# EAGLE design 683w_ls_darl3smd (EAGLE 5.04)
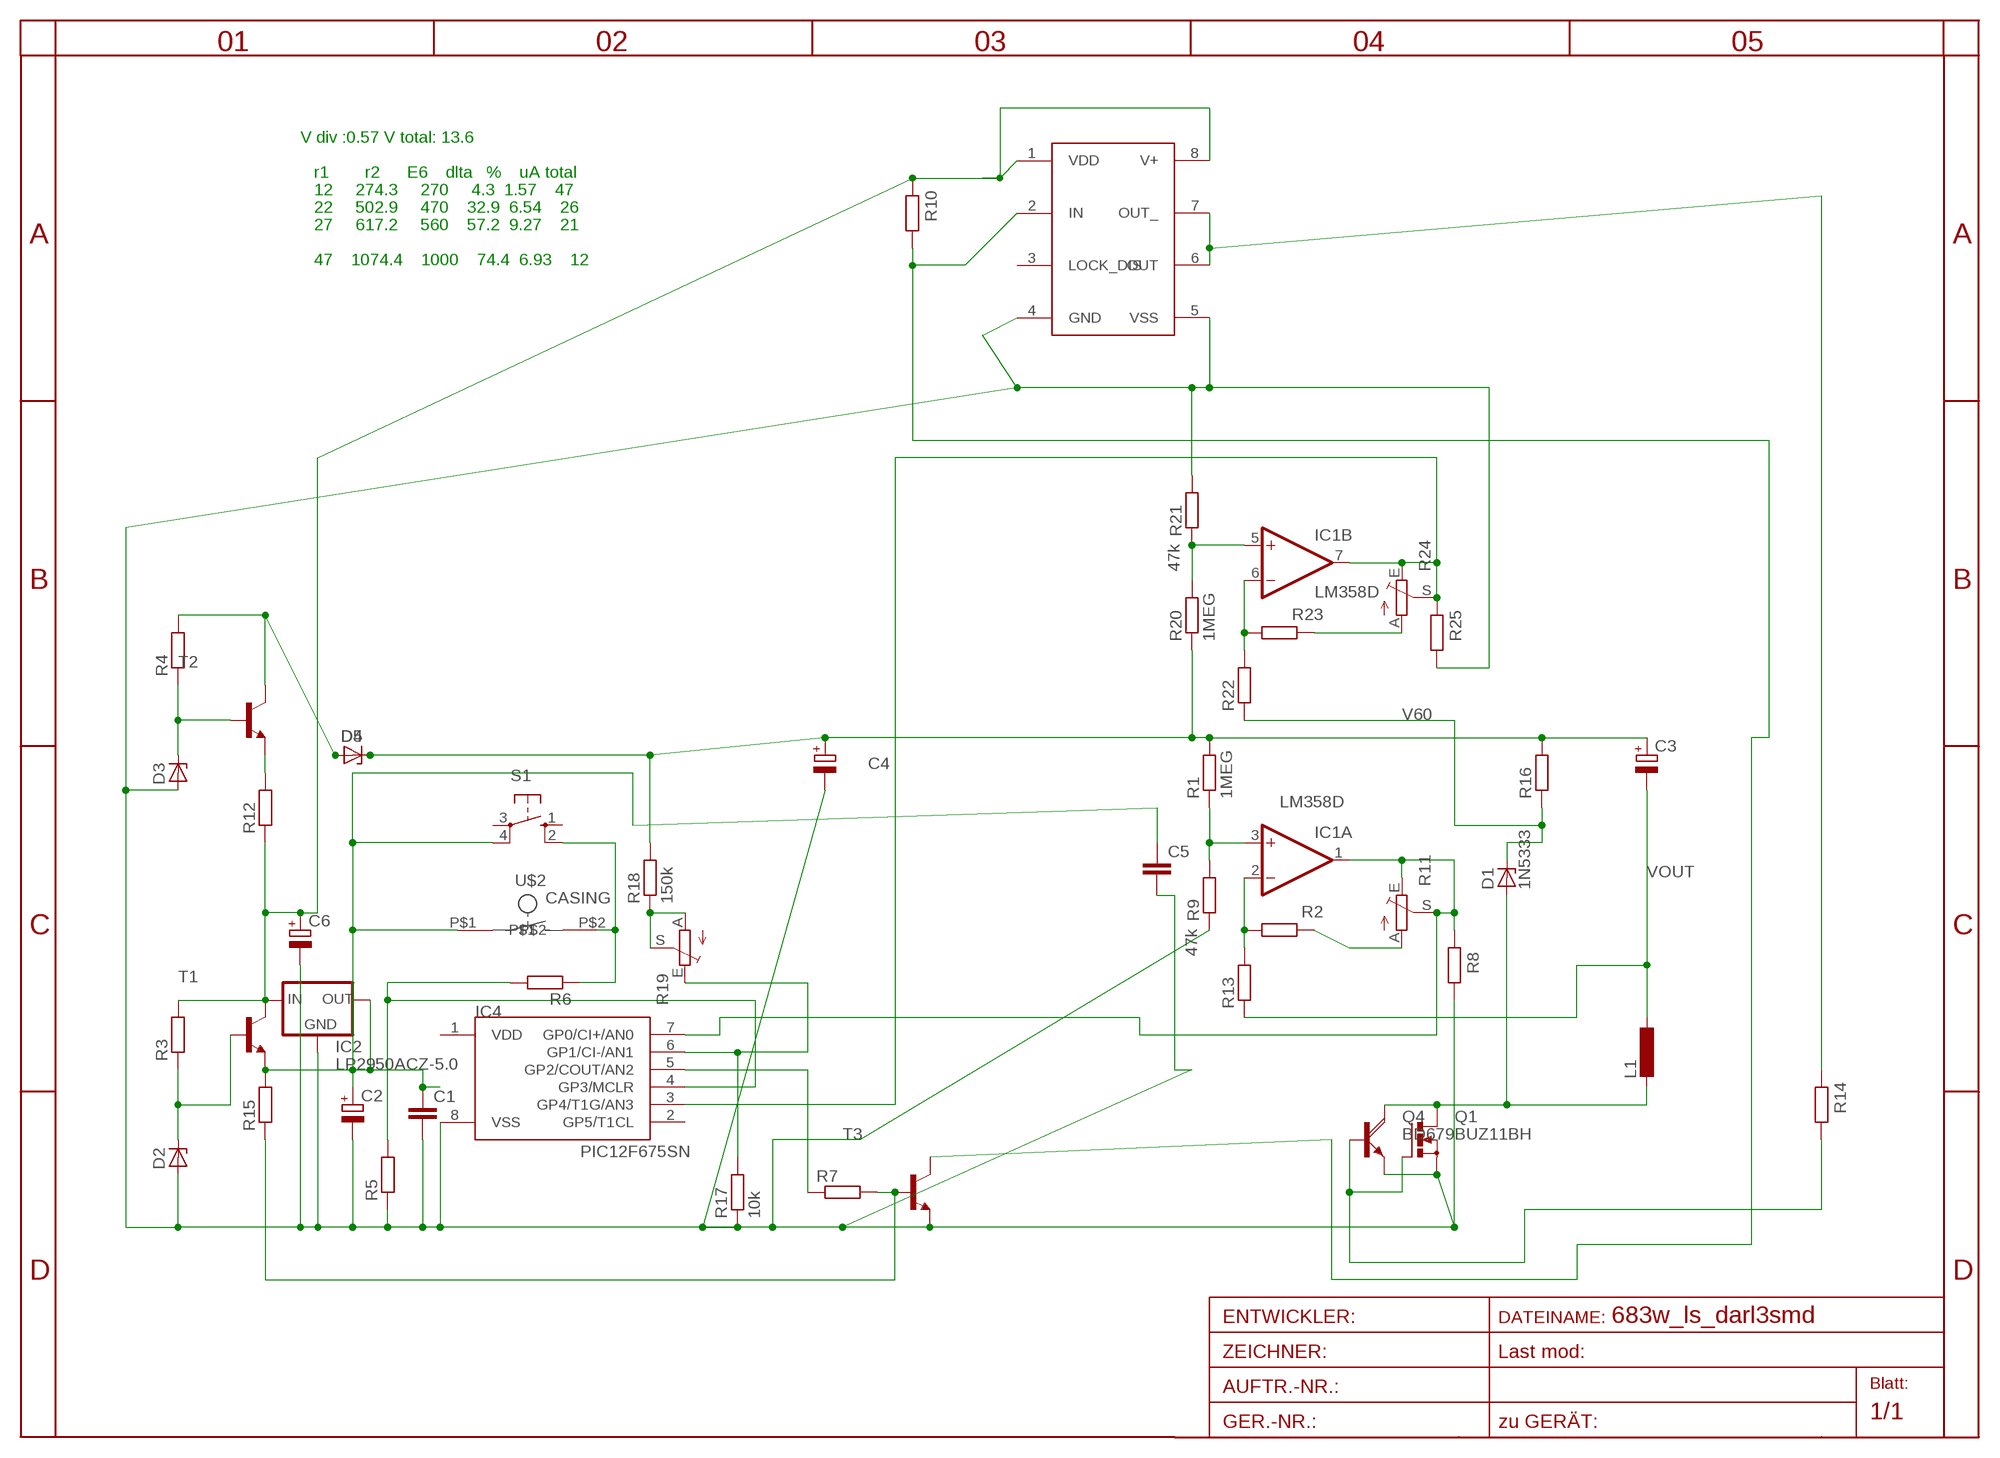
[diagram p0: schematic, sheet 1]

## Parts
C1  C-EUC1206  [C1206]
C2  CPOL-EUSANYO_SMD_E12  [SANYO-OSCON_SMD_E12]
C3  CPOL-EUE5-8.5  [E5-8,5]
C4  CPOL-EUE5-8.5  [E5-8,5]
C5  C-EUC1206  [C1206]
C6  CPOL-EUSANYO_SMD_E12  [SANYO-OSCON_SMD_E12]
D1  1N5333  [C1702-15]
D2  ZENER-DIODESOT23  [SOT23]
D3  ZENER-DIODESMB  [SMB]
D4  ZENER-DIODESMB  [SMB]
D5  ZENER-DIODESMB  [SMB]
IC1  LM358D  [SO08]
IC2  LP2950ACZ-5.0  [TO92]
IC3  TC4432X  [SO-08]
IC4  PIC12F675SN  [SO-08]
L1  L-EU2200-15.24  [2200-15.24]
Q1  BUZ11BH  [TO220BH]
Q4  BD679  [TO126AV]
R1  1MEG  R-EU_R0805  [R0805]
R2  R-EU_R0805  [R0805]
R3  R-EU_R0805  [R0805]
R4  R-EU_R0805  [R0805]
R5  R-EU_R0805  [R0805]
R6  R-EU_M1206  [M1206]
R7  R-EU_R0805  [R0805]
R8  R-EU_R0805  [R0805]
R9  47k  R-EU_R0805  [R0805]
R10  R-EU_R0805  [R0805]
R11  TRIM_EU-CA6V  [CA6V]
R12  R-EU_R0805  [R0805]
R13  R-EU_R0805  [R0805]
R14  R-EU_0207/10  [0207/10]
R15  R-EU_R0805  [R0805]
R16  R-EU_0411/12  [0411/12]
R17  10k  R-EU_R0805  [R0805]
R18  150k  R-EU_R0805  [R0805]
R19  TRIM_EU-CA6V  [CA6V]
R20  1MEG  R-EU_R0805  [R0805]
R21  47k  R-EU_R0805  [R0805]
R22  R-EU_R0805  [R0805]
R23  R-EU_R0805  [R0805]
R24  TRIM_EU-CA6V  [CA6V]
R25  R-EU_R0805  [R0805]
S1  10-XX  [B3F-10XX]
T1  BC846BLT1-NPN-SOT23-BEC  [SOT23-BEC]
T2  BC846BLT1-NPN-SOT23-BEC  [SOT23-BEC]
T3  BC846BLT1-NPN-SOT23-BEC  [SOT23-BEC]
U$2  CASING  [CASING]

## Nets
BB: IC3.2(IN) R10.1 T3.C
HOTSPOT: D1.A L1.2 Q1.D Q4.C
N$1: IC1.1(A:OUT) IC4.7(GP0/CI+/AN0) R8.2 R11.E R11.S
N$2: R2.1 R11.A
N$3: Q1.G Q4.B R14.1
N$5: IC4.4(GP3/MCLR) R5.2 R6.2
N$6: D2.3(C) R3.1 T1.B
N$7: R6.1 S1.2(S1) U$2.P$2
N$8: IC1.3(A:+IN) R1.1 R9.2
N$9: IC4.5(GP2/COUT/AN2) R7.1
N$11: IC3.6(OUT) IC3.7(OUT_) R14.2
N$12: D3.C R4.1 T2.B
N$13: R18.1 R19.A R19.S
N$15: IC1.2(A:-IN) R2.2 R13.2
N$17: R7.2 R15.1 T3.B
N$21: D4.A D5.A R4.2 T2.C
N$22: R12.2 T2.E
N$23: D1.C R16.1 R22.1
N$24: IC1.5(B:+IN) R20.2 R21.1
N$25: IC1.6(B:-IN) R22.2 R23.2
N$26: IC4.6(GP1/CI-/AN1) R17.2 R19.E
N$27: R23.1 R24.A
N$28: IC1.7(B:OUT) IC4.3(GP4/T1G/AN3) R24.E R24.S R25.2
V60: C3.+ C4.+ D4.C D5.C R1.2 R16.2 R18.2 R20.1
V+: C1.1 C2.+ C5.1 IC2.1(OUT) R15.2 S1.4(P1) T1.E U$2.P$1
V-: C1.2 C2.- C4.- C5.2 C6.- D2.1(A) D3.A IC2.2(GND) IC3.4(GND) IC3.5(VSS) IC4.8(VSS) Q1.S Q4.E R5.1 R8.1 R9.1 R17.1 R21.2 R25.1 T3.E
VCC: C6.+ IC2.3(IN) IC3.1(VDD) IC3.8(V+) R3.2 R10.2 R12.1 T1.C
VOUT: C3.- L1.1 R13.1
Unconnected: IC3.3(LOCK_DIS) IC4.2(GP5/T1CL) S1.1(S) S1.3(P)

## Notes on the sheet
- V div :0.57 V total: 13.6
- r1        r2      E6    dlta   %    uA total
- 12     274.3     270     4.3  1.57    47
- 22     502.9     470    32.9  6.54    26
- 27     617.2     560    57.2  9.27    21
- 47    1074.4    1000    74.4  6.93    12

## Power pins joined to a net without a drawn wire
V+: IC1.8(P:V+)
V-: IC1.4(P:V-)
VDD: IC4.1(VDD)

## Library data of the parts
C1 C5 = rcl:C-EU: CAPACITOR, European symbol
C2-C4 C6 = rcl:CPOL-EU: POLARIZED CAPACITOR, European symbol
D1 = diode-1:1N5333: Z DIODE
D2-D5 = diode-1:ZENER-DIODE: Z-Diode
IC1 = linear4:LM358: OP AMP
IC2 = v-reg:LP2950?*: Source: http://cache.national.com/ds/LP/LP2950.pdf
IC3 = microchip:TC4432
IC4 = microchip-5:PIC12F6*: uPC nW 1k Program Flash memory 2x Timer Comparator 10b A/D converter/ 4xIN
L1 = rcl:L-EU: INDUCTOR, European symbol
Q1 = transistor-power:BUZ11: N-CHANNEL MOS FET
Q4 = transistor-power:BD679: NPN DARLINGTON TRANSISTOR
R1-R6 R8-R10 R12 R14 R15 R20 R21 R23 R25 = rcl:R-EU_: RESISTOR, European symbol
R7 R13 R16-R18 R22 = rcl-2:R-EU_: RESISTOR, European symbol
R11 R19 R24 = pot:TRIM_EU-: POTENTIOMETER
S1 = switch-omron:10-XX: OMRON SWITCH
T1-T3 = transistor-neu-to92:*-NPN-: NPN Transistror
U$2 = button:CASING

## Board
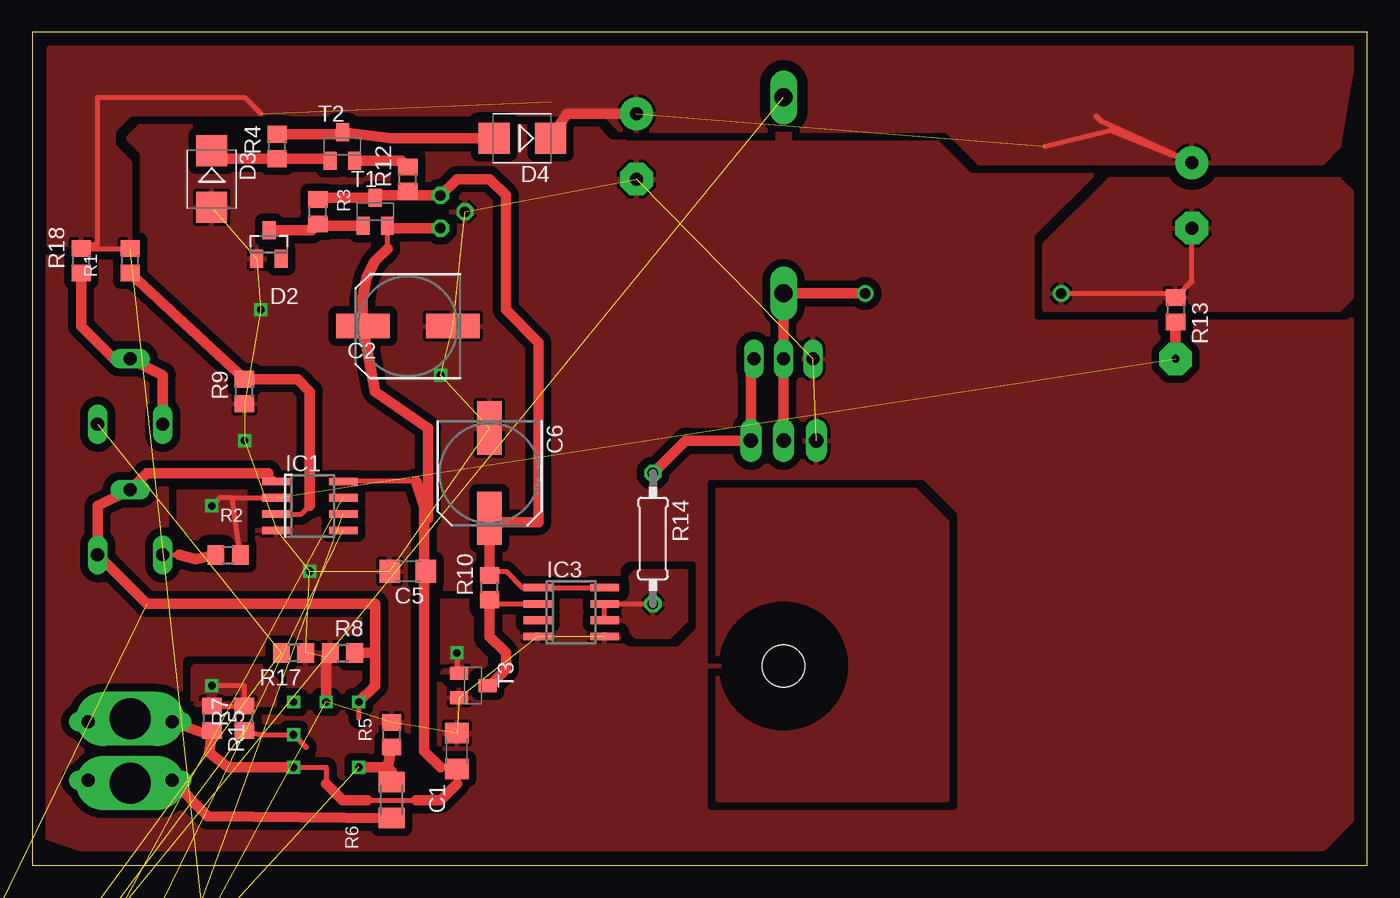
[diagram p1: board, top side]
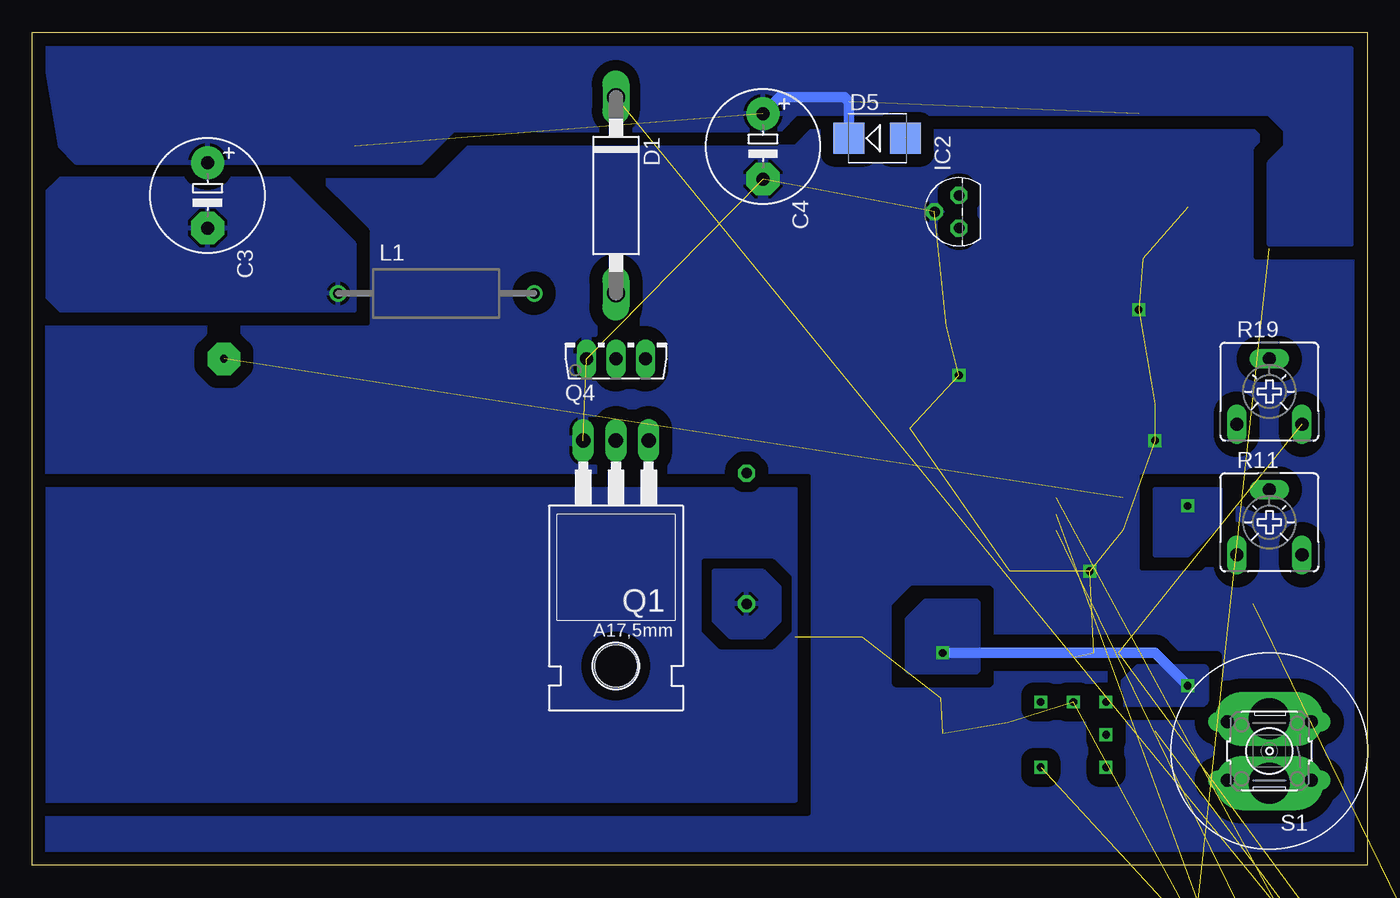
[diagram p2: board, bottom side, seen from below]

Size 103.81 x 64.76 mm. Coordinates in mm from the lower left corner, seen from the top.
Outline: 0,0 103.81,0 103.81,64.76 0,64.76 0,0
Copper layers (1*16): Top 0.035mm / dielectric 1.5mm / Bottom 0.035mm
Design rules "default": minimum track width 10mil, minimum drill 24mil, track to track 8mil, track to pad 8mil, pad to pad 8mil, via to via 8mil, smd to smd 8mil, copper to edge 40mil, drill to drill 8mil, minimum pad ring 10mil, minimum via ring 8mil, stop-mask expansion 4mil, vias tented up to drill 0mil, thermal gap 10mil

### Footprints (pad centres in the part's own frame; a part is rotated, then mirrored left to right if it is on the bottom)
C1206 = smd 1.6 x 1.8: 1 -1.4,0; 2 1.4,0
SANYO-OSCON_SMD_E12 = smd 4.15 x 1.9: + 3.5,0; - -3.5,0
E5-8,5 = drill 1.016 pad 2.54 round: + -2.54,0 | drill 1.016 pad 2.54 octagon: - 2.54,0
C1702-15 = drill 1.397 long: A 7.62,0; C -7.62,0
SOT23 = smd 1 x 1.4: 1 -0.95,-1.1; 2 0.95,-1.1; 3 0,1.1
SMB = smd 2.4 x 2.4: A 2.2,0; C -2.2,0
SO08 = smd 0.6 x 2.2: 1 -1.905,-2.6; 2 -0.635,-2.6; 3 0.635,-2.6; 4 1.905,-2.6; 5 1.905,2.6; 6 0.635,2.6; 7 -0.635,2.6; 8 -1.905,2.6
TO92 = drill 0.813 octagon: 1 -1.27,0; 2 0,1.905; 3 1.27,0
SO-08 = smd 0.6 x 2.2: 1 -1.905,-2.6; 2 -0.635,-2.6; 3 0.635,-2.6; 4 1.905,-2.6; 5 1.905,2.6; 6 0.635,2.6; 7 -0.635,2.6; 8 -1.905,2.6
2200-15.24 = drill 0.8 pad 1.27 round: 1 -7.62,0; 2 7.62,0
TO220BH = drill 1.118 long: D 0,-6.35; G -2.54,-6.35; S 2.54,-6.35 | hole 3.302: 0,11.176
TO126AV = drill 1.016 long: B 2.286,-1.27; C 0,-1.27; E -2.286,-1.27
R0805 = smd 1.3 x 1.5: 1 -0.95,0; 2 0.95,0
M1206 = smd 1.6 x 2: 1 -1.4,0; 2 1.4,0
CA6V = drill 1.016 long: A -2.54,-2.54; E 2.54,-2.54; S 0,2.54
0207/10 = drill 0.813 octagon: 1 -5.08,0; 2 5.08,0
0411/12 = drill 0.914 octagon: 1 -6.35,0; 2 6.35,0
B3F-10XX = drill 1.016 long: 1 -3.251,2.261; 2 3.251,2.261; 3 -3.251,-2.261; 4 3.251,-2.261
SOT23-BEC = smd 1 x 1.4: B -0.95,-1.1; C 0,1.1; E 0.95,-1.1
CASING = drill 3.2 pad 3.81 long: P$1 -2.5,0; P$2 2.5,0

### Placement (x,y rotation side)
C1  33.02,8.89 90 top
C2  29.21,41.91 180 top
C3  90.17,52.07 270 bottom
C4  46.99,55.88 270 bottom
C5  29.21,22.86 180 top
C6  35.56,30.48 270 top
D1  58.42,52.07 270 bottom
D2  18.41,48.26 0 top
D3  13.97,53.34 270 top
D4  38.1,56.52 180 top
D5  38.1,56.52 0 bottom
IC1  21.59,27.94 270 top
IC2  31.75,50.8 90 bottom
IC3  41.91,19.68 270 top
IC4  not placed on the board
L1  72.39,44.45 0 bottom
Q1  58.42,26.67 180 bottom
Q4  58.42,40.64 0 bottom
R1  7.62,46.99 90 top
R2  15.24,24.13 0 top
R3  22.23,50.8 90 top
R4  19.05,55.88 90 top
R5  27.94,10.16 270 top
R6  27.94,5.08 90 top
R7  16.51,11.43 90 top
R8  24.13,16.51 0 top
R9  16.51,36.83 90 top
R10  35.56,21.59 90 top
R11  7.62,26.67 0 bottom
R12  29.21,53.34 90 top
R13  88.9,43.18 270 top
R14  48.26,25.4 270 top
R15  13.97,11.43 270 top
R16  not placed on the board
R17  20.32,16.51 180 top
R18  3.81,46.99 90 top
R19  7.62,36.83 0 bottom
R20  not placed on the board
R21  not placed on the board
R22  not placed on the board
R23  not placed on the board
R24  not placed on the board
R25  not placed on the board
S1  7.62,8.89 180 bottom
T1  26.67,50.8 0 top
T2  24.13,55.88 0 top
T3  34.29,13.97 270 top
U$2  7.62,8.89 270 bottom

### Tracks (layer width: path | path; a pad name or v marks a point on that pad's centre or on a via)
BB
  Top 0.406: T3.C 35.56,13.97 | IC3.2 35.88,20.32 R10.1
  Top 0.813: R10.1 35.56,17.78 36.83,16.51 36.83,15.24 35.56,13.97
HOTSPOT
  Top 0.813: L1.2 D1.A Q4.C Q1.D
N$1  (via drill 0.6)  (1 unrouted)
  Top 0.406: v25.4,12.7 25.4,11.43 | 18.36,30.48 IC1.1
  Top 0.813: 26.67,16.51 26.67,20.32 8.89,20.32 R11.E 5.08,27.94 R11.S 8.89,30.48 18.36,30.48 | 26.67,16.51 26.67,13.97 v25.4,12.7 | 26.67,16.51 R8.2
N$2
  Top 0.406: R11.A 11.43,24.13
  Top 0.813: 11.43,24.13 12.7,23.81 R2.1
N$3
  Top 0.406: 55.88,39.12 Q4.B
  Top 0.813: R14.1 50.8,33.02 Q1.G 55.88,39.12
N$4  (via drill 0.6)
  other vias: 20.32,12.7
N$5  (1 unrouted)
  Top 0.813: 27.62,7.62 25.4,7.62 | 27.62,7.62 R5.2 | R6.2 27.94,7.3 27.62,7.62
N$6
  Top 0.406: 22.38,49.7 R3.1 21.73,49.36
  Top 0.813: 22.38,49.7 T1.B | D2.3 21.73,49.36
N$7
  Top 0.813: R6.1 13.65,3.81 S1.2 10.63,6.39 U$2.P$2
N$8
  Top 0.406: 21.59,27.94 20.95,27.3 IC1.3
  Top 0.813: R1.1 R9.2 20.64,37.78 21.59,36.83 21.59,27.94
N$9  (1 unrouted)
  Top 0.406: 21.34,9.14 20.32,10.16 17.78,10.16 R7.1
N$10  (via drill 0.6)
  other vias: 22.86,12.7
N$11
  Top 0.406: R14.2 IC3.7 IC3.6
  pour Bottom (isolate 0.813): 45.72,21.59 46.99,22.86 50.8,22.86 50.8,19.05 49.53,17.78 46.99,17.78 45.72,19.05
  pour Top (isolate 0.813): 45.72,21.59 46.99,22.86 50.8,22.86 50.8,19.05 49.53,17.78 46.99,17.78 45.72,19.05
N$12
  Top 0.406: D3.C 13.97,55.88
  Top 0.813: T2.B 23.03,54.93 R4.1 14.58,54.93 D3.C
N$13
  Top 0.406: R19.S 6.35,39.37
  Top 0.813: 6.35,39.37 3.81,41.91 R18.1 | R19.A 10.16,38.1 R19.S
N$15  (via drill 0.6, 0.6 pad 2.54)  (1 unrouted)
  Top 0.406: 15.55,28.57 IC1.2 | R2.2 15.55,28.57 | 15.55,28.57 14.61,28.57 v13.97,27.94
  Top 0.813: v88.9,39.37 R13.2
  pour Top (isolate 0.813, rank 3): 11.43,29.21 16.51,29.21 16.51,24.13 13.97,24.13 11.43,26.67
  pour Bottom (isolate 0.813, rank 3): 11.43,29.21 16.51,29.21 16.51,24.13 13.97,24.13 11.43,26.67
N$16  (via drill 0.6)
  other vias: 20.32,10.16
N$17  (via drill 0.6)
  Top 0.406: R15.1 R7.2 16.51,13.97 v13.97,13.97 | v33.02,16.51 33.02,15.09 T3.B
  Bottom 0.813: v13.97,13.97 16.51,16.51 v33.02,16.51
  pour Top (isolate 0.813, rank 3): 12.7,15.24 17.78,15.24 20.32,12.7 12.7,12.7
  pour Top (isolate 0.813, rank 3): 30.48,20.32 34.29,20.32 35.56,19.05 35.56,15.24 30.48,15.24
  pour Bottom (isolate 0.813, rank 3): 30.48,20.32 34.29,20.32 35.56,19.05 35.56,15.24 30.48,15.24
  pour Bottom (isolate 0.813, rank 3): 12.7,15.24 17.78,15.24 20.32,12.7 12.7,12.7
N$18  (via drill 0.6)
  other vias: 20.32,7.62
N$19  (via drill 0.6)
  other vias: 25.4,7.62
N$20
  pour Top (isolate 0.813, rank 3): 53.34,29.21 68.58,29.21 71.12,26.67 71.12,5.08 53.34,5.08
  pour Bottom (isolate 0.813, rank 3): 44.45,29.21 102.87,29.21 102.87,5.08 44.45,5.08
N$21  (1 unrouted)
  Top 0.813: D5.A 27.94,56.52 T2.C 23.98,56.83 R4.2
N$22
  Top 0.813: T2.E 28.72,54.78 R12.2
N$23  (2 unrouted)
N$24  (2 unrouted)
N$25  (2 unrouted)
N$26  (2 unrouted)
N$27  (1 unrouted)
N$28  (4 unrouted)
V60  (4 unrouted)
  Top 0.406: R1.2 R18.2 3.49,48.26 5.08,48.26 5.08,59.69 16.51,59.69 17.78,58.42 | 83.19,57.78 82.87,58.1 | 83.19,57.78 C3.+ 83.82,57.15 78.74,55.88 | 83.19,57.78 82.72,58.25
  Top 0.813: C4.+ 41.57,58.42 D5.C
  Bottom 0.813: D5.C 40.3,59.35 40.64,59.69 45.72,59.69 C4.+
  pour Top (isolate 0.813, rank 4): 102.87,63.5 1.27,63.5 1.27,48.26 7.62,48.26 7.62,54.61 6.35,55.88 6.35,57.15 7.62,58.42 44.45,58.42 45.72,57.15 71.12,57.15 73.66,54.61 100.33,54.61 101.6,55.88
  pour Bottom (isolate 0.813, rank 4): 102.87,63.5 1.27,63.5 1.27,48.26 7.62,48.26 7.62,54.61 6.35,55.88 6.35,57.15 7.62,58.42 44.45,58.42 45.72,57.15 71.12,57.15 73.66,54.61 100.33,54.61 101.6,55.88
V+
  Top 0.406: 13.69,10.16 13.77,8.77 | 33.02,6.35 C1.1 32.89,7.62 31.75,7.62 | 22.86,6.35 22.86,7.62 20.32,7.62 | 13.97,10.24 R15.2 | 29.84,29.84 IC1.8 | 27.79,49.53 T1.E 27.62,47.94 | 30.48,22.86 C5.1 | 30.48,26.67 30.8,26.99 | 26.04,5.08 29.84,5.08
  Top 0.813: 13.69,10.16 S1.4 10.63,11.39 U$2.P$1 | 33.02,6.35 31.75,5.08 29.84,5.08 | 22.86,6.35 24.13,5.08 26.04,5.08 | 13.97,10.24 13.77,8.77 15.24,7.62 20.32,7.62 | 29.84,29.84 30.48,27.94 30.48,26.67 30.48,22.86 30.48,8.89 31.75,7.62 | 27.79,49.53 IC2.1 | 27.62,47.94 26.67,46.99 26.02,45.72 25.71,44.14 C2.+ 26.67,36.83 30.8,33.97 30.8,26.99
V-  (via drill 0.6)  (24 unrouted)
  Top 0.406: 22.86,16.19 R8.1
  Top 0.813: 22.86,12.7 22.86,16.19
  other vias: 17.78,43.18 16.51,33.02 21.59,22.86 31.75,38.1
  pour Bottom (isolate 1.016, rank 5): 102.87,60.96 102.87,0 90.17,0 1.27,1.27 1.27,58.42
  pour Top (isolate 0.61, rank 5): 1.27,63.5 99.06,63.5 102.87,59.69 102.87,3.81 100.33,1.27 3.81,1.27 0,2.54
VCC
  Top 0.406: IC3.8 IC3.1 38.1,21.59 36.83,22.86 35.88,22.86 R10.2 | 35.56,26.67 C6.+ | 26.84,52.07 T1.C | 22.38,51.9 R3.2
  Top 0.813: R10.2 35.56,26.67 39.37,26.67 39.37,40.64 36.83,43.18 36.83,52.07 35.56,53.34 33.02,53.34 IC2.3 29.21,52.07 | T1.C 22.38,51.9 | 29.21,52.07 26.84,52.07 | 29.21,52.07 R12.1
VOUT
  Top 0.406: L1.1 88.58,44.45 R13.1 90.17,45.4 C3.-
  pour Top (isolate 0.813, rank 3): 101.6,53.34 102.87,52.07 102.87,44.45 101.6,43.18 78.74,43.18 78.74,48.26 83.82,53.34
  pour Bottom (isolate 0.813, rank 3): 101.6,53.34 102.87,52.07 102.87,44.45 101.6,43.18 78.74,43.18 78.74,48.26 83.82,53.34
